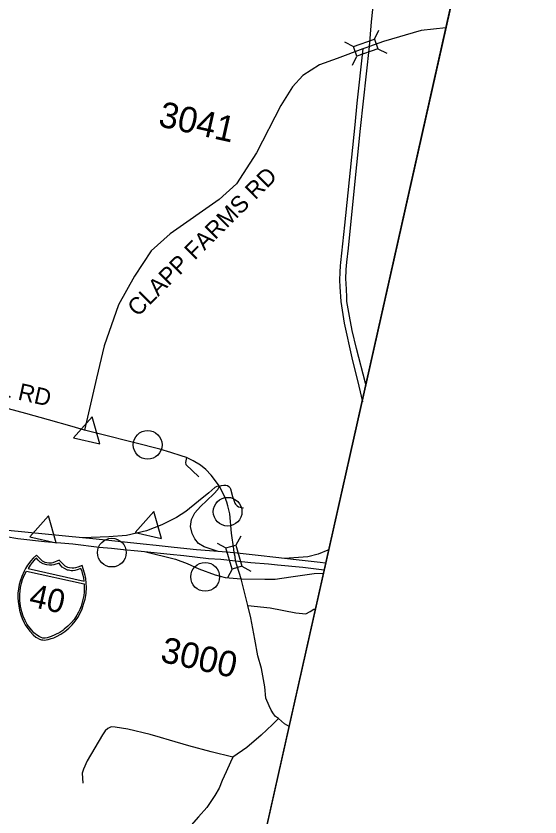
# Model space of a CAD drawing. Extents: x 1784499 to 1786147, y 841097 to 842538.
# Drawn here: x 1784963.4 to 1785099.6, y 842114.2 to 842322.5 of the extents above; entities that cross this region are included whole.
import ezdxf

# ---------------------------------------------------------------- set-up
doc = ezdxf.new("R2010")
doc.units = 0
for name, color, linetype in [('DEV CONE PLAN VIEW CELL', 7, 'Continuous'), ('Exist Road Primary Interstate Divided Center Attributed', 7, 'Continuous'), ('Exist Road Primary Interstate Ramp 1 Lane Attributed', 7, 'Continuous'), ('Exist Road Primary Interstate Shield CELL', 7, 'Continuous'), ('Exist Road Primary Interstate Shield Number Label', 7, 'Continuous'), ('Exist Road Secondary Structure Standard Bridge CELL', 7, 'Continuous'), ('Exist Road Secondary Type 51 Attributed', 7, 'Continuous'), ('Exist Road Secondary Type 51 Number Label', 7, 'Continuous'), ('Old_Level_40', 7, 'Continuous'), ('Prop DSN Text', 7, 'Continuous'), ('Prop Road Primary Interstate Projected', 7, 'Continuous'), ('Scratch_Level_3', 7, 'Continuous')]:
    doc.layers.add(name, color=color, linetype=linetype)

msp = doc.modelspace()

# ---------------------------------------------------------------- linework, layer by layer
at = {"layer": 'DEV CONE PLAN VIEW CELL'}
for points in [[(1784983.21, 842218.25), (1784978.41, 842212.76), (1784985.21, 842211.24)], [(1784999.23, 842193.67), (1784994.44, 842188.19), (1785001.23, 842186.66)], [(1784971.86, 842192.5), (1784967.06, 842187.02), (1784973.86, 842185.49)]]:
    msp.add_lwpolyline(points, close=True, dxfattribs=at)
for centre in [(1784997.65, 842210.96), (1785018.44, 842193.58), (1784988.36, 842182.95), (1785012.61, 842176.64)]:
    msp.add_circle(centre, 3.74, dxfattribs=at)
at = {"layer": 'Exist Road Primary Interstate Divided Center Attributed'}
for points in [[(1785055.3, 842314.59), (1785055.85, 842320.96), (1785056.74, 842329.12), (1785056.94, 842333.35), (1785057.11, 842337.08), (1785056.88, 842342.99), (1785056.6, 842346.6), (1785055.76, 842353.95), (1785054.64, 842364.97), (1785053.89, 842371.63), (1785053.38, 842377.03)], [(1784980.73, 842186.78), (1784936.5, 842191.15), (1784907.31, 842193.9), (1784903.59, 842194.28), (1784892.4, 842193.99)], [(1784892.58, 842192.67), (1784899.97, 842192.68), (1784903.35, 842192.69), (1784910.9, 842192.36), (1784921.42, 842191.2), (1784931.61, 842190.14), (1784940.34, 842189.28), (1784948.6, 842188.51), (1784957.77, 842187.67), (1784963.9, 842186.64), (1784970.81, 842185.8), (1784978.25, 842185.25), (1784985.05, 842184.39), (1784988.3, 842184.13), (1784991.42, 842183.79), (1784995.13, 842183.43), (1784996.87, 842183.27)], [(1785015.98, 842183.25), (1785010.39, 842183.68), (1785004.54, 842184.25), (1784999.85, 842184.76), (1784996.46, 842185.14), (1784984.26, 842186.41), (1784980.73, 842186.78)], [(1784996.87, 842183.27), (1785003.5, 842182.5), (1785007.09, 842182.17), (1785013.44, 842181.45), (1785016.7, 842181.2), (1785020.52, 842180.81)], [(1785020.16, 842182.91), (1785015.98, 842183.25)], [(1785033.2, 842181.4), (1785031, 842181.66), (1785026.4, 842182.22), (1785020.16, 842182.91)], [(1785020.52, 842180.81), (1785024.45, 842180.41), (1785029.11, 842180.07), (1785031.41, 842179.79), (1785038.01, 842179.14), (1785043.55, 842178.44)], [(1785043.94, 842180.17), (1785043.82, 842180.19), (1785042.54, 842180.34), (1785037.02, 842181.02), (1785033.2, 842181.4)]]:
    msp.add_lwpolyline(points, dxfattribs=at)
at = {"layer": 'Exist Road Primary Interstate Ramp 1 Lane Attributed'}
for points in [[(1785016.35, 842200.22), (1785015.68, 842200.18), (1785015.1, 842199.91), (1785013.59, 842198.47), (1785010.87, 842196.36), (1785007.54, 842193.67), (1785005.12, 842192.08), (1785001.38, 842190.2), (1784997.36, 842188.61), (1784992.12, 842187.42), (1784987.53, 842187.03), (1784980.73, 842186.78)], [(1785015.98, 842183.25), (1785012.33, 842184.42), (1785010.88, 842185.34), (1785009.96, 842186.5), (1785009.22, 842187.96), (1785008.79, 842189.72), (1785009.08, 842191.55), (1785009.94, 842193.25), (1785011.38, 842194.94), (1785013.02, 842196.47), (1785014.83, 842198.19), (1785015.92, 842199.37), (1785016.35, 842200.22)], [(1784996.87, 842183.27), (1785004.88, 842181.24), (1785007.93, 842180.08), (1785010.93, 842178.7), (1785015.2, 842177.15), (1785017.77, 842176.46), (1785021.95, 842176.11)], [(1785044.72, 842183.66), (1785044.53, 842183.54), (1785041.99, 842182.56), (1785039.31, 842181.81), (1785033.2, 842181.4)], [(1785021.95, 842176.11), (1785028.09, 842176.04), (1785030.8, 842176.02), (1785034.85, 842176.65), (1785040.97, 842177.53), (1785043.35, 842177.56)]]:
    msp.add_lwpolyline(points, dxfattribs=at)
at = {"layer": 'Exist Road Primary Interstate Shield CELL'}
for points in [[(1784970.05, 842160.27), (1784970.38, 842160.23), (1784970.83, 842160.22), (1784971.28, 842160.26), (1784971.81, 842160.36), (1784972.6, 842160.6), (1784973.24, 842160.8), (1784974, 842161.1), (1784975.06, 842161.7), (1784976.15, 842162.43), (1784977.17, 842163.31), (1784978.01, 842164.15), (1784978.8, 842165.15), (1784979.49, 842166.1), (1784980.12, 842167.21), (1784980.62, 842168.32), (1784981.01, 842169.5), (1784981.39, 842170.82), (1784981.64, 842172.35), (1784981.73, 842173.96), (1784981.69, 842174.97), (1784981.58, 842176.2), (1784981.44, 842177.01), (1784981.02, 842178.47), (1784980.61, 842179.61), (1784979.55, 842179.17), (1784978.87, 842178.99), (1784978.47, 842178.9), (1784978.07, 842178.91), (1784977.36, 842178.99), (1784976.93, 842179.1), (1784976.55, 842179.28), (1784976.22, 842179.44), (1784975.97, 842179.64), (1784974.69, 842180.94), (1784972.97, 842180.31), (1784972.63, 842180.23), (1784972.29, 842180.24), (1784971.96, 842180.22), (1784971.44, 842180.31), (1784971.05, 842180.41), (1784970.67, 842180.57), (1784970.36, 842180.71), (1784970.05, 842180.96), (1784968.73, 842182.28), (1784967.94, 842181.54), (1784967.26, 842180.79), (1784966.46, 842179.69), (1784965.93, 842178.82), (1784965.52, 842178.1), (1784964.92, 842176.74), (1784964.5, 842175.53), (1784964.28, 842174.66), (1784963.95, 842172.44), (1784963.92, 842171.22), (1784963.96, 842170.23), (1784964.31, 842168.01), (1784964.66, 842166.74), (1784965, 842165.8), (1784965.53, 842164.72), (1784965.82, 842164.19), (1784967.04, 842162.52), (1784967.9, 842161.6), (1784968.61, 842160.99), (1784968.96, 842160.76), (1784969.52, 842160.46)], [(1784968.76, 842181.53), (1784968.26, 842181.04), (1784967.66, 842180.37), (1784967.13, 842179.64), (1784966.58, 842178.83), (1784981.2, 842175.55), (1784981.03, 842176.39), (1784980.84, 842177.23), (1784980.61, 842178.01), (1784980.3, 842178.79), (1784979.36, 842178.46), (1784978.7, 842178.31), (1784978.18, 842178.25), (1784977.76, 842178.25), (1784977.12, 842178.34), (1784976.84, 842178.42), (1784976.01, 842178.82), (1784975.47, 842179.2), (1784974.98, 842179.7), (1784974.62, 842180.23), (1784973.31, 842179.79), (1784972.74, 842179.68), (1784972.12, 842179.66), (1784971.45, 842179.73), (1784970.48, 842180.06), (1784969.76, 842180.5), (1784969.17, 842181)], [(1784981.12, 842174.81), (1784981.19, 842174.36), (1784981.2, 842173.4), (1784981.15, 842172.67), (1784981.09, 842171.83), (1784980.73, 842170.44), (1784980.34, 842169.02), (1784980.02, 842168.19), (1784979.67, 842167.45), (1784979.23, 842166.65), (1784978.58, 842165.59), (1784977.83, 842164.74), (1784976.91, 842163.81), (1784975.97, 842163.03), (1784975.57, 842162.71), (1784974.83, 842162.21), (1784973.54, 842161.58), (1784972.61, 842161.16), (1784971.53, 842160.81), (1784971, 842160.71), (1784970.4, 842160.71), (1784969.95, 842160.85), (1784969.42, 842161.13), (1784968.99, 842161.35), (1784968.11, 842162.12), (1784967.43, 842162.84), (1784966.33, 842164.25), (1784965.79, 842165.26), (1784965.34, 842166.41), (1784964.96, 842167.56), (1784964.61, 842169.05), (1784964.46, 842170.5), (1784964.46, 842172.04), (1784964.63, 842173.87), (1784964.85, 842174.96), (1784965.15, 842175.99), (1784965.38, 842176.52), (1784965.66, 842177.17), (1784966.16, 842178.16)]]:
    msp.add_lwpolyline(points, close=True, dxfattribs=at)
at = {"layer": 'Exist Road Secondary Structure Standard Bridge CELL'}
for p, q in [((1785056.63, 842316.44), (1785057.78, 842318.79)), ((1785048.84, 842315.74), (1785051.19, 842314.59)), ((1785057.47, 842313.96), (1785059.83, 842312.81)), ((1785050.91, 842309.7), (1785052.06, 842312.06)), ((1785021.85, 842187.21), (1785020.59, 842184.91)), ((1785015.72, 842185.43), (1785018.01, 842184.17)), ((1785019.65, 842178.67), (1785018.39, 842176.38)), ((1785022.17, 842179.4), (1785024.46, 842178.13))]:
    msp.add_line(p, q, dxfattribs=at)
for points in [[(1785051.19, 842314.59), (1785056.62, 842316.45), (1785057.49, 842313.92), (1785052.06, 842312.06)], [(1785020.59, 842184.91), (1785022.18, 842179.4), (1785019.6, 842178.66), (1785018.01, 842184.17)]]:
    msp.add_lwpolyline(points, close=True, dxfattribs=at)
at = {"layer": 'Exist Road Secondary Type 51 Attributed'}
for points in [[(1785075.17, 842319.42), (1785068.72, 842318.69), (1785058.94, 842315.84), (1785055.3, 842314.59)], [(1785053.58, 842313.93), (1785046.94, 842311.41), (1785042.37, 842309.78), (1785037.99, 842307), (1785035.33, 842304.05), (1785032.26, 842299.21), (1785025.96, 842286.91), (1785020.75, 842278.81), (1785016.23, 842274.8), (1785003.52, 842265.84), (1784998.55, 842261.42), (1784994.2, 842254.88), (1784990.09, 842247.39), (1784986.37, 842236.73), (1784984.4, 842228.32)], [(1785055.3, 842314.59), (1785054.38, 842314.24), (1785053.58, 842313.93)], [(1784984.4, 842228.32), (1784981.23, 842214.77)], [(1784981.23, 842214.77), (1784978.04, 842215.71), (1784971.85, 842217.46), (1784965.96, 842219.11), (1784956.88, 842221.58), (1784950.36, 842223.17), (1784944.92, 842224.66), (1784939.07, 842226.2)], [(1785007.77, 842207.68), (1785006.35, 842208.15), (1785003.69, 842208.94), (1785000.8, 842209.82), (1784994.34, 842211.53), (1784985.4, 842213.71), (1784981.23, 842214.77)], [(1785007.77, 842207.68), (1785007.49, 842206.41), (1785007.58, 842205.87), (1785010.92, 842202.68)], [(1785016.35, 842200.22), (1785014.15, 842203.08), (1785012.77, 842204.54), (1785011.38, 842205.71), (1785009.52, 842206.83), (1785007.77, 842207.68)], [(1785016.35, 842200.22), (1785016.89, 842200.41), (1785017.45, 842200.48), (1785017.95, 842200.52), (1785018.41, 842200.38), (1785018.76, 842200.18), (1785019, 842199.92), (1785019.22, 842199.54), (1785019.74, 842197.56), (1785020.12, 842196.29), (1785020.3, 842195.81), (1785020.46, 842195.54), (1785020.72, 842195.25), (1785020.96, 842195.08), (1785021.27, 842194.88), (1785021.69, 842194.75), (1785022.58, 842194.57)], [(1785020.16, 842182.91), (1785020.02, 842183.88), (1785019.49, 842187.98), (1785018.99, 842193), (1785018.51, 842195.12), (1785018.23, 842196.07), (1785017.8, 842197.17), (1785016.35, 842200.22)], [(1785020.52, 842180.81), (1785020.41, 842181.9), (1785020.16, 842182.91)], [(1785021.95, 842176.11), (1785020.92, 842179.42), (1785020.52, 842180.81)], [(1785023.71, 842169.15), (1785021.95, 842176.11)], [(1785031.71, 842139.78), (1785030.93, 842140.36), (1785030.41, 842141.05), (1785029.75, 842141.98), (1785029.22, 842143.06), (1785028.42, 842145.08), (1785028.15, 842148.08), (1785027.28, 842152.77), (1785026.29, 842156.1), (1785025.51, 842160.45), (1785024.45, 842165.99), (1785023.71, 842169.15)], [(1785023.71, 842169.15), (1785029.47, 842168.57), (1785036.19, 842167.26), (1785038.74, 842166.99), (1785039.88, 842167.64), (1785040.82, 842168.23), (1785041.28, 842168.31)], [(1785031.71, 842139.78), (1785030.11, 842138.27), (1785027.2, 842135.5), (1785023.4, 842132.3), (1785019.82, 842129.73)], [(1785034.41, 842137.69), (1785033.22, 842138.4), (1785031.71, 842139.78)], [(1785019.82, 842129.73), (1785014.19, 842131.16), (1785008.35, 842132.74), (1785003.3, 842134.21), (1785001, 842134.84), (1784998.32, 842135.65), (1784992.48, 842137.07), (1784989.2, 842137.59), (1784988.14, 842137.61), (1784987.3, 842137.17), (1784986.64, 842136.57), (1784985.88, 842135.57), (1784981.93, 842128.82), (1784981, 842126.59), (1784980.67, 842125.6), (1784980.84, 842123.02)], [(1785019.82, 842129.73), (1785019.16, 842128.46), (1785018.05, 842125.95), (1785017.07, 842123.72), (1785016.25, 842121.67), (1785015.13, 842119.81), (1785013.01, 842116.7), (1785010.89, 842114.27), (1785008.94, 842112.04), (1785005.49, 842106.94), (1785003.91, 842105.07), (1785002.45, 842102.86)]]:
    msp.add_lwpolyline(points, dxfattribs=at)
at = {"layer": 'Old_Level_40'}
msp.add_line((1785099.64, 842428.53), (1784986.93, 841925.94), dxfattribs=at)
at = {"layer": 'Prop Road Primary Interstate Projected'}
for points in [[(1785053.58, 842313.93), (1785052.06, 842299.81), (1785051.5, 842294.21), (1785048.82, 842268.09), (1785047.77, 842258.4), (1785047.69, 842257.53), (1785047.6, 842255.87), (1785047.55, 842253.78), (1785047.63, 842252.08), (1785047.91, 842248.21), (1785048.7, 842242.63), (1785050.77, 842233.56), (1785052.51, 842226.23), (1785053.51, 842222.13)], [(1785054.36, 842226.63), (1785054.26, 842227.05), (1785051.98, 842236.02), (1785050.81, 842240.7), (1785050.1, 842244.42), (1785049.47, 842248.26), (1785049.41, 842249.57), (1785049.28, 842253.02), (1785049.19, 842254.09), (1785049.3, 842256.57), (1785049.45, 842258.47), (1785049.87, 842262.15), (1785051.04, 842274.37), (1785052.97, 842293.25), (1785055.3, 842314.59)]]:
    msp.add_lwpolyline(points, dxfattribs=at)
at = {"layer": 'Scratch_Level_3'}
msp.add_lwpolyline([(1785039.41, 842390.83), (1785050.23, 842439.1), (1784611.48, 842537.49), (1784510.23, 842085.98), (1784998.27, 841976.54), (1785088.7, 842379.78)], close=True, dxfattribs=at)

# ---------------------------------------------------------------- texts
at = {"layer": 'Exist Road Primary Interstate Shield Number Label'}
msp.add_text('40', height=6.075, rotation=347.3599, dxfattribs=at).set_placement((1784966.56, 842169.02))
at = {"layer": 'Exist Road Secondary Type 51 Number Label'}
for s, p in [('3041', (1785000.15, 842293.91)), ('3000', (1785000.69, 842154.64))]:
    msp.add_text(s, height=6.665, rotation=347.3599, dxfattribs=at).set_placement(p)
at = {"layer": 'Prop DSN Text'}
for s, rotation, p in [('CLAPP FARMS RD', 44.8916, (1784995.06, 842244.08)), ('McCONNELL RD', 347.336, (1784927.38, 842230.95))]:
    msp.add_text(s, height=4.3971, rotation=rotation, dxfattribs=at).set_placement(p)

doc.saveas('drawing.dxf')
